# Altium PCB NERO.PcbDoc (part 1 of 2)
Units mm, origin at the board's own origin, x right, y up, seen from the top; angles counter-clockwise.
Board outline 53.3 x 68.53 mm, 2 copper layers (Top Layer[1], Bottom Layer[2]), stack 1.636 mm thick; 112 components, 60 nets, 397 pads, 225 vias.
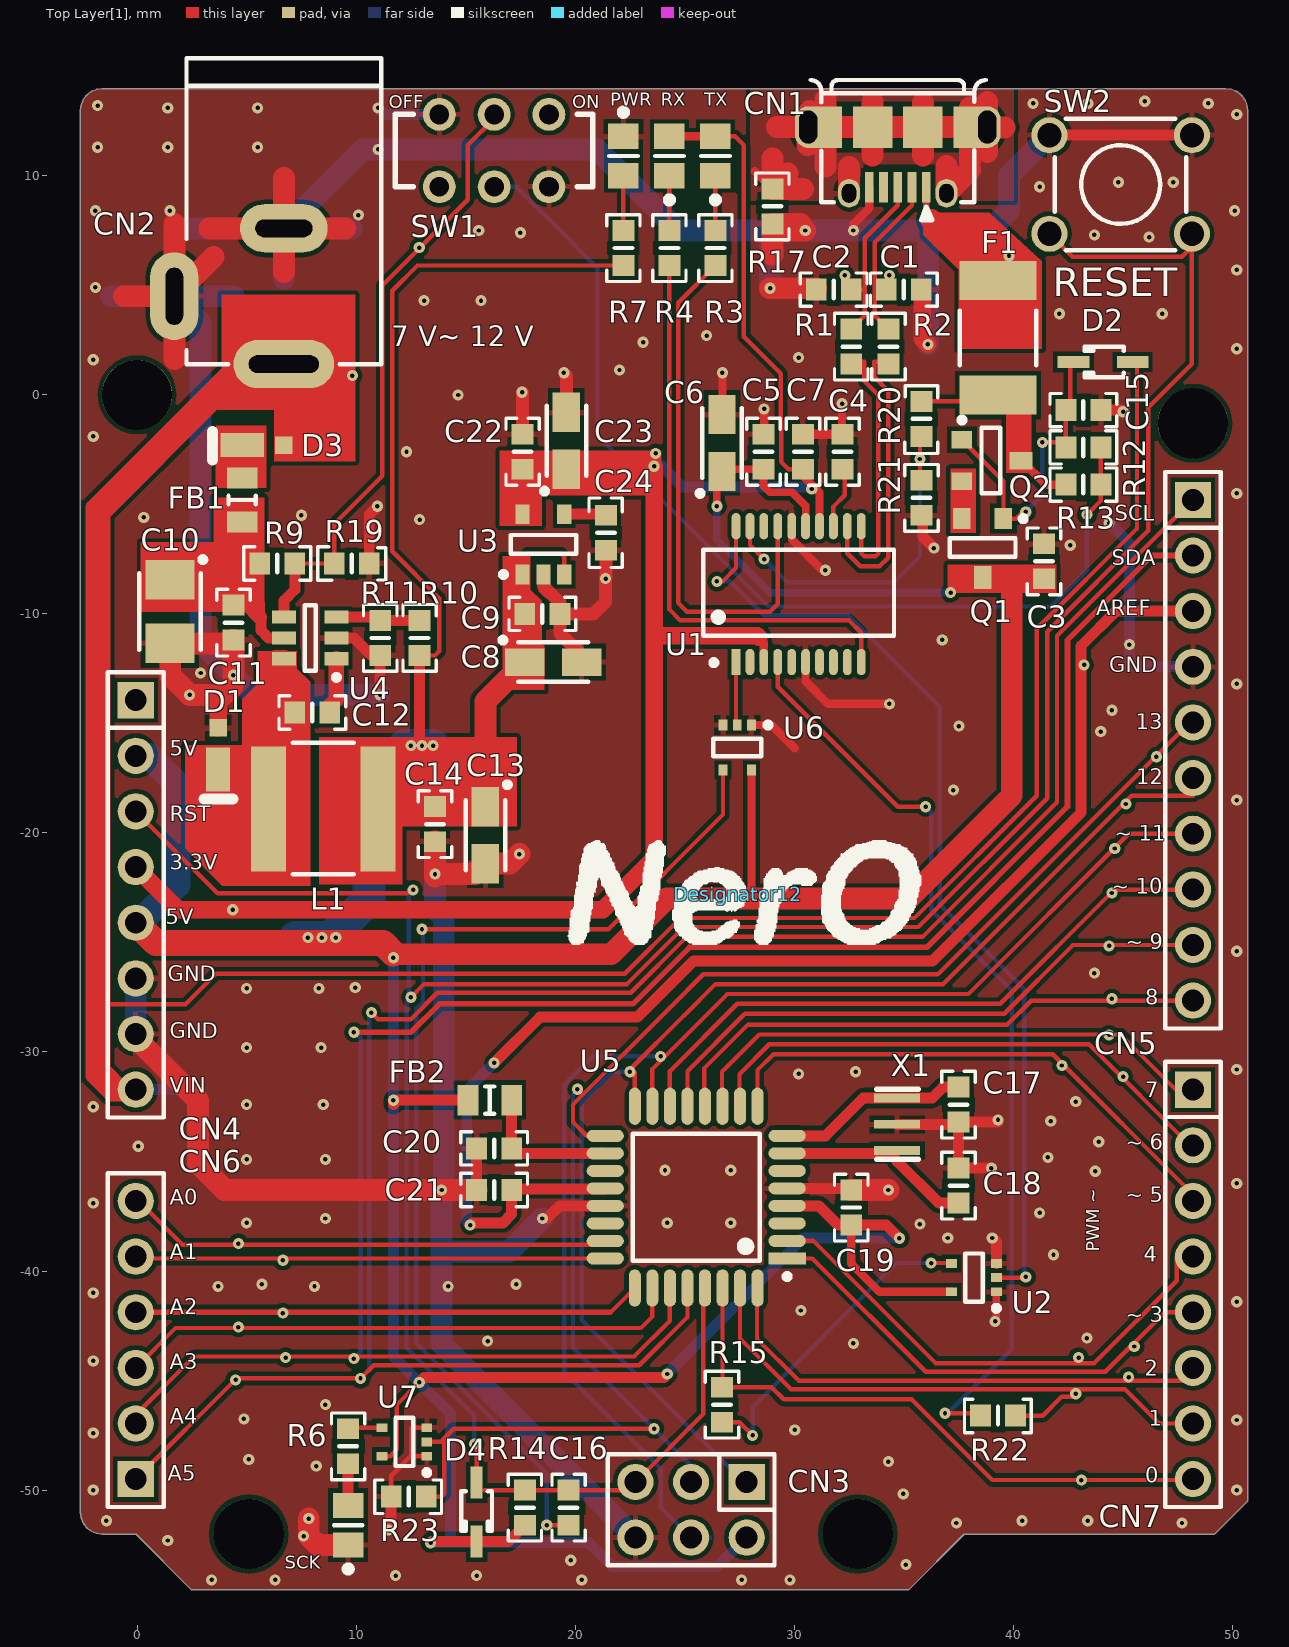
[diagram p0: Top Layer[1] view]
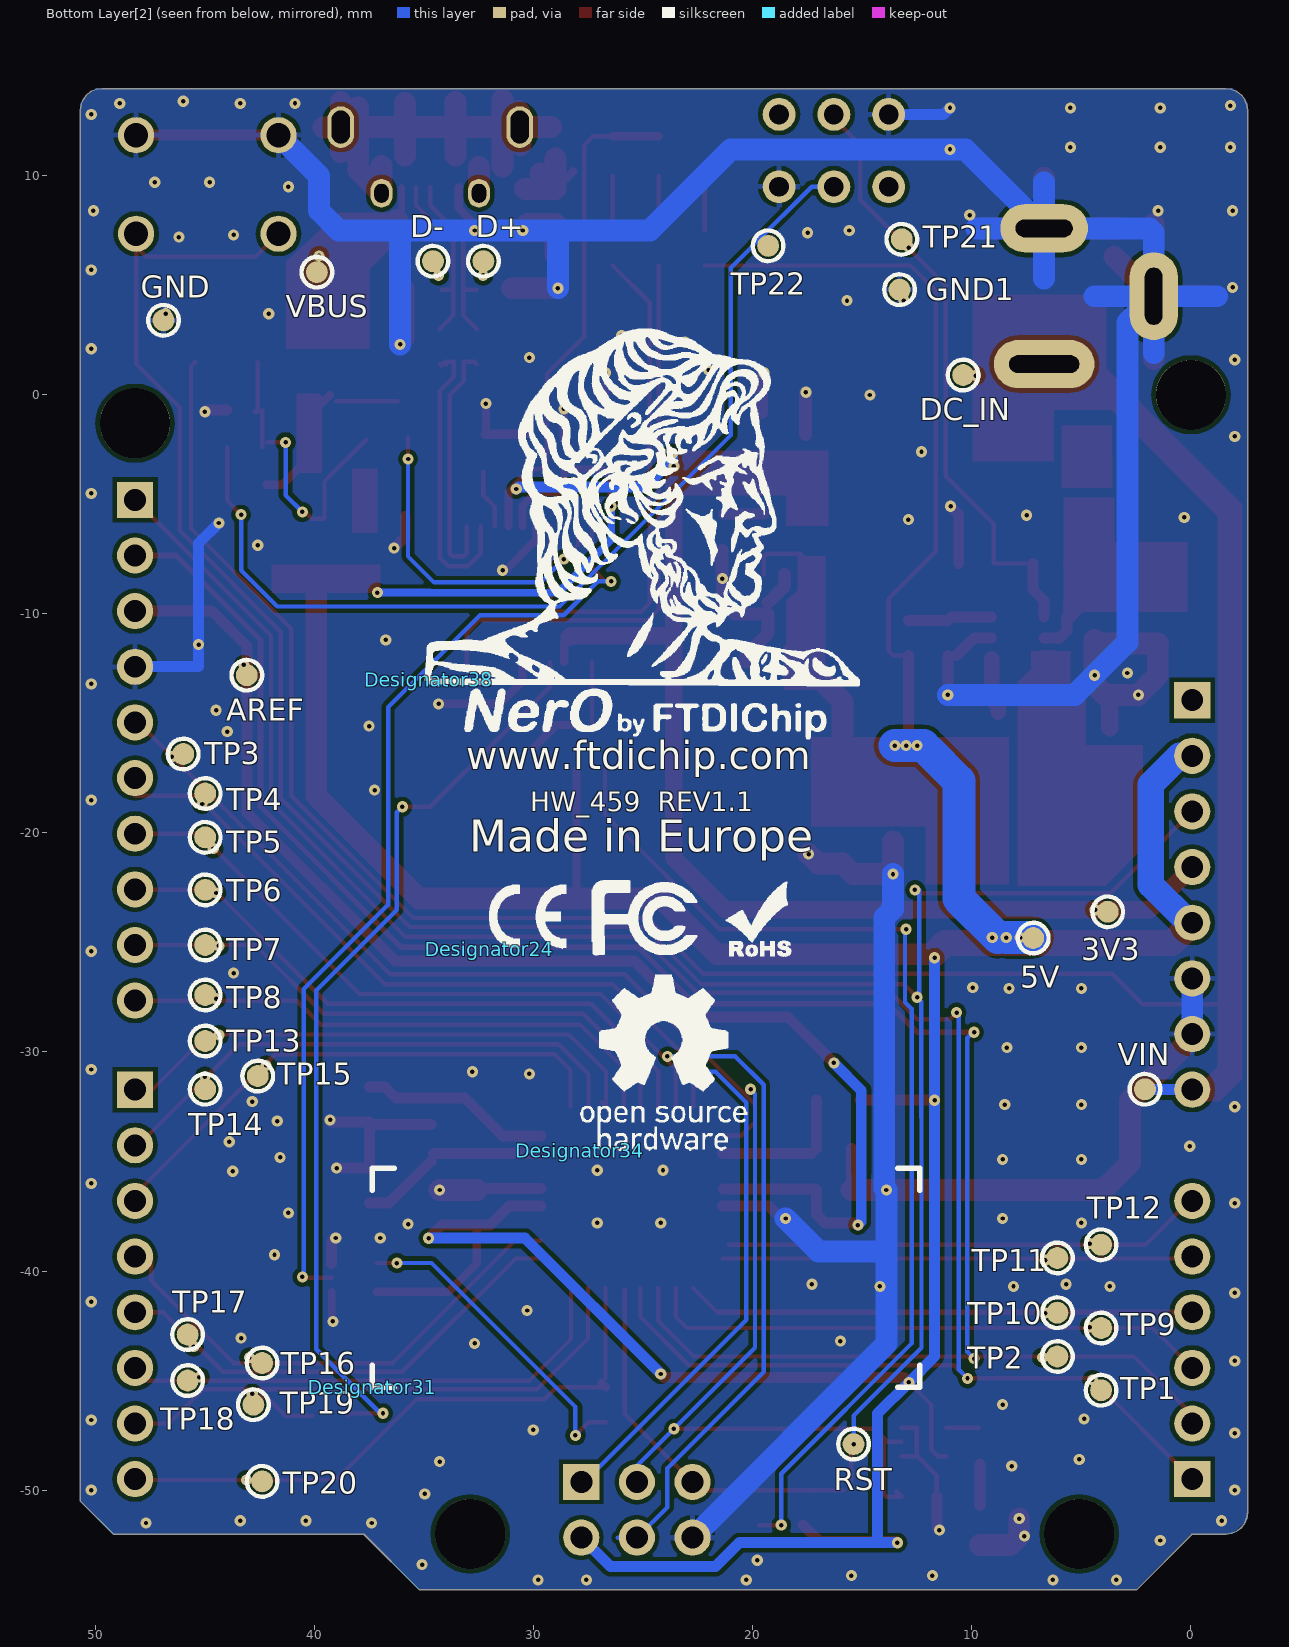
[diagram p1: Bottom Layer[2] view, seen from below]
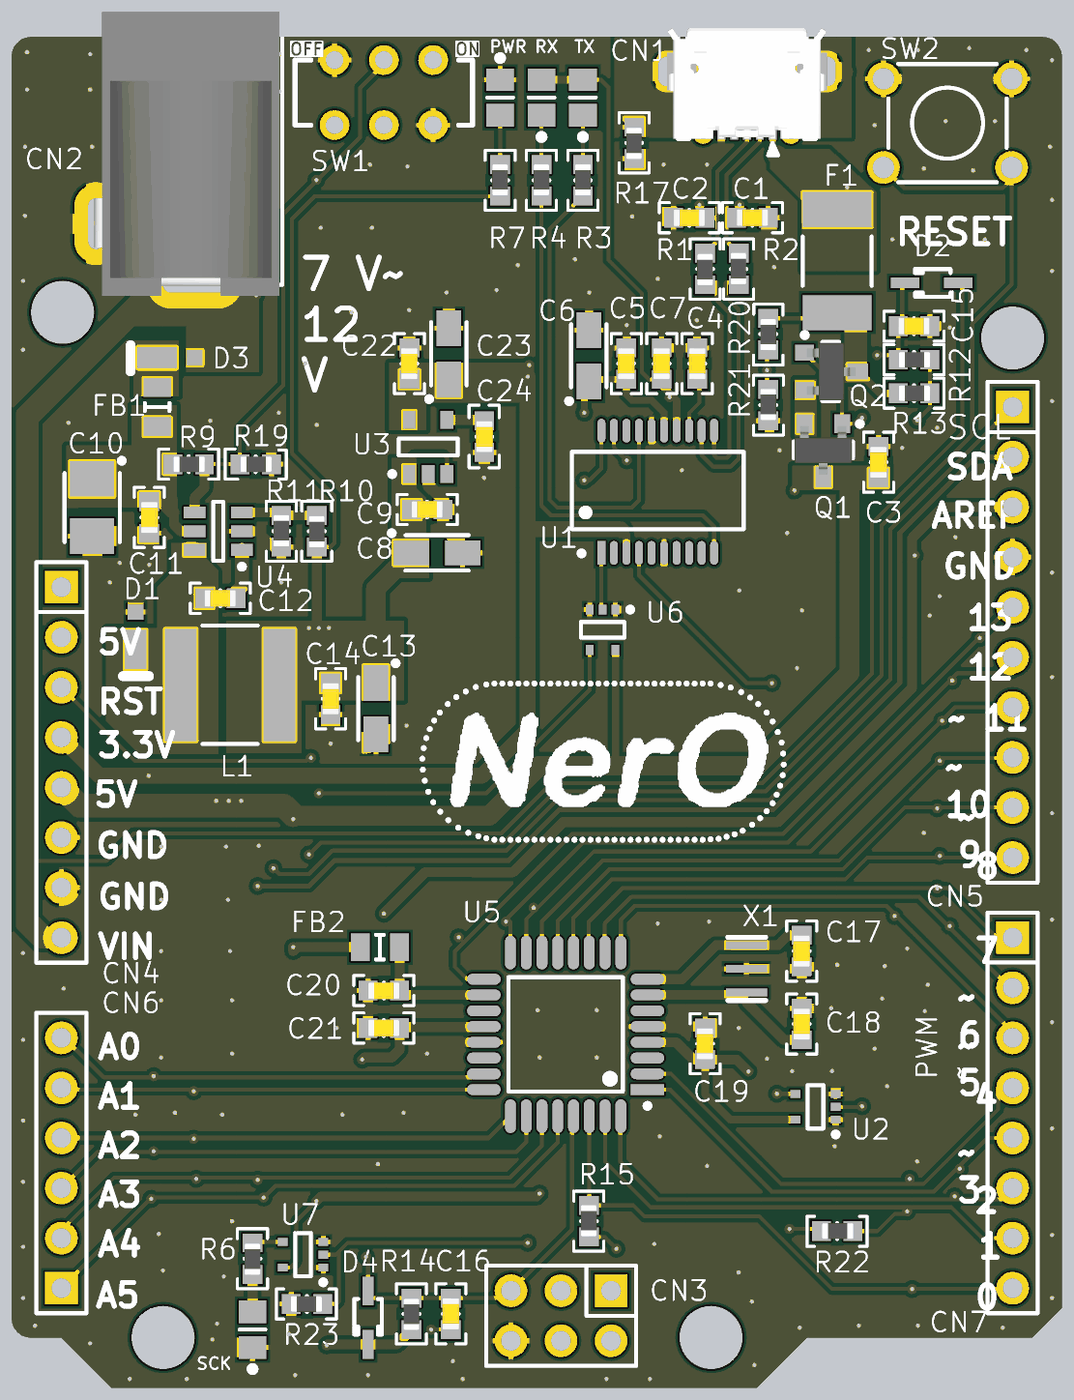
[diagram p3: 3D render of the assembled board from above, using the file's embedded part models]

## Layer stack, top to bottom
Top Layer[1]: signal copper 0.018
Dielectric: prepreg 1.6, FR4, Dk 4.8
Bottom Layer[2]: signal copper 0.018

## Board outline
-2.464,13.472 -2.295,13.684 -2.083,13.853 -1.851,13.938 -1.597,13.98 49.693,13.98 49.968,13.938 50.201,13.853 50.413,13.684 50.561,13.472 50.666,13.239 50.709,12.986 50.709,-50.492 49.185,-52.016 37.759,-52.016 35.22,-54.555 2.487,-54.555 -0.052,-52.016 -1.597,-52.016 -1.851,-51.973 -2.083,-51.889 -2.295,-51.719 -2.464,-51.508 -2.549,-51.275 -2.591,-51.021 -2.591,12.986 -2.549,13.239

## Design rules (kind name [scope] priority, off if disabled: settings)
Clearance [All] p1: gap=0.2
ComponentClearance [All] p1: gap=0.2 collisioncheckmode=3 verticalgap=0.2 showdistances=FALSE
DiffPairsRouting [All] p1: maxlimit=0.254 minlimit=0.254 mostfreqgap=0.254 maxuncoupledlength=12.7
FabricationTestPointUsage TestPointUsage [All] p1: valid=0 allowmultiple=FALSE
FabricationTestpoint Testpoint [All] p1: side=3 testpointundercomponent=TRUE minsize=1.016 maxsize=2.54 preferedsize=1.524 minholesize=0 maxholesize=1.016 preferedholesize=0.813 testpointgrid=0.025 allowsidetop=TRUE allowsidebottom=TRUE usegrid=TRUE gridtolerance=0
HoleSize [All] p1: absolutevalues=TRUE maxlimit=10 minlimit=0.025 maxpercent=80.000 minpercent=20.000
HoleToHoleClearance [All] p1: gap=0.25 allowstackedmicrovias=TRUE
MinimumSolderMaskSliver [All] p1: minsoldermaskwidth=0.1
PlaneClearance [All] p1: clearance=0.4
PlaneConnect [All] p1: planeconnectstyle=Relief reliefexpansion=0.4 reliefentries=4 reliefconductorwidth=0.25 reliefairgap=0.25
PolygonConnect PolygonConnect_VIA [isvia vs InNet(gnd)] p1: connectstyle=Direct reliefconductorwidth=0.25 reliefentries=4 polygonreliefangle="90 Angle"
PolygonConnect [All] p2: connectstyle=Relief reliefconductorwidth=0.25 reliefentries=4 polygonreliefangle="90 Angle"
RoutingVias [All] p1: holewidth=0.4 width=0.7 viastyle="Through Hole" minholewidth=0.4 minwidth=0.7 maxholewidth=0.6 maxwidth=0.9
SilkToSilkClearance [All] p1: silktosilkclearance=0.2
SilkscreenOverComponentPads [All] p1: minsilkscreentomaskgap=0.254
SolderMaskExpansion [All] p1: expansion=0.1
Width [All] p1: maxlimit=10 minlimit=0.2 preferedwidth=0.2 minimp=50.000000 maximp=50.000000 favimp=50.000000
17 further rules are at their usual default settings.

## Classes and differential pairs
component class nero: 3V3 5V AREF C1 C2 C3 C4 C5 C6 C7 C8 C9 C10 C11 C12 C13 C14 C15 C16 C17 C18 C19 C20 C21 C22 C23 C24 CN1 CN2 CN3 CN4 CN5 CN6 CN7 D1 D2 D3 D4 D+ D- DC_IN F1 FB1 FB2 GND GND1 L1 PWR Q1 Q2 R1 R2 R3 R4 R6 R7 R9 R10 R11 R12 R13 R14 R15 R17 R19 R20 R21 R22 R23 RST RX SCK SW1 SW2 TP21 TP22 TX U1 U2 U3 U4 U5 U6 U7 VBUS VIN X1
component class SCH_Revision_History: TP1 TP2 TP3 TP4 TP5 TP6 TP7 TP8 TP9 TP10 TP11 TP12 TP13 TP14 TP15 TP16 TP17 TP18 TP19 TP20
differential pair D: +D_P -D_N
differential pair USB: +USB_P -USB_N

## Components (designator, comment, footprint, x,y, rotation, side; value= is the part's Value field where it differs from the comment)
3V3 "SMT_TP" TP_SMT_1MM 3.8,-23.6 r180 bottom
5V "SMT_TP" TP_SMT_1MM 7.2,-24.8 r180 bottom
AREF "SMT_TP" TP_SMT_1MM 43.1,-12.8 r270 bottom
C1 "DNP" CAPC1608-0603 35,4.8 r0 top
C2 "DNP" CAPC1608-0603 31.8,4.8 r180 top
C3 "0.1UF" CAPC1608-0603 41.4,-7.6 r90 top
C4 "0.1UF" CAPC1608-0603 32.2,-2.6 r270 top
C5 "0.1UF" CAPC1608-0603 28.6,-2.6 r90 top
C6 "10uF" CAPM-A-3216-18 26.7,-2.2 r90 top
C7 "0.1UF" CAPC1608-0603 30.4,-2.6 r90 top
C8 "10uF" CAPM-A-3216-18 19,-12.2 r0 top
C9 "0.1UF" CAPC1608-0603 18.5,-10 r0 top
C10 "10UF/25V" CAPM-B-3528-21 1.5,-9.9 r270 top
C11 "0.1UF" CAPC1608-0603 4.4,-10.4 r270 top
C12 "0.1UF" CAPC1608-0603 8,-14.5 r180 top
C13 "10uF" CAPM-A-3216-18 15.9,-20.1 r270 top
C14 "0.1UF" CAPC1608-0603 13.6,-19.6 r270 top
C15 "1nF" CAPC1608-0603 43.2,-0.7 r0 top
C16 "0.1UF" CAPC1608-0603 19.7,-50.8 r90 top
C17 "15pF" CAPC1608-0603 37.5,-32.4 r90 top
C18 "15pF" CAPC1608-0603 37.5,-36.1 r270 top
C19 "0.1UF" CAPC1608-0603 32.6,-37.1 r90 top
C20 "0.1UF" CAPC1608-0603 16.3,-34.4 r180 top
C21 "0.1UF" CAPC1608-0603 16.3,-36.3 r0 top
C22 "0.1uF" CAPC1608-0603 17.6,-2.6 r90 top
C23 "10uF" CAPM-A-3216-18 19.6,-2.1 r90 top
C24 "10nF" CAPC1608-0603 21.4,-6.3 r270 top
CN1 "CN USB" CN_USB_MICRO_HOUSING 32.5,9.2 r0 top
CN2 "2.1mm PwrJack" "CN_2.1mm Power Socket routed pins" 6.7,7.6 r270 top
CN3 "TC2030-IDC-FP" CN_HDR2X3 27.829,-49.627 r180 top locked
CN4 "HEADER 8" CN_HDR1X8 -0.06,-13.94 r270 top locked
CN5 "HEADER 10" CN_HDR1X10 48.2,-4.796 r270 top locked
CN6 "HEADER 6" HDR1X6 -0.06,-49.5 r90 top locked
CN7 "HEADER 8" CN_HDR1X8 48.2,-31.72 r270 top locked
D1 "MSS1P3L" DIODE_MSS1P3L 3.7,-15.2 r90 top
D2 "1N4148" SOD-323 44.1,1.5 r0 top
D3 "MSS1P3L" DIODE_MSS1P3L 6.7,-2.3 r0 top
D4 "1N4148" SOD-323 15.5,-51 r90 top
D+ "SMT_TP" TP_SMT_1MM 32.3,6.1 r180 bottom
D- "SMT_TP" TP_SMT_1MM 34.6,6.1 r180 bottom
DC_IN "SMT_TP" TP_SMT_1MM 10.4,0.9 r180 bottom
Designator12 "Comment" LOGO_NERO1 19.9,-25.1 r0 top locked
Designator24 "Comment" logo_fcc_3 32.024,-25.318 r180 bottom
Designator31 "Comment" label_location 37.375,-45.305 r180 bottom
Designator34 "Comment" logo_oshw2 27.9,-34.5 r180 bottom
Designator38 "Comment" logo_nero_ftdi 34.8,-13 r180 bottom
F1 "1.1A" "Fuse_0ZCG Series" 39.3,2.6 r270 top
FB1 "600R/2A" IND_C2012-0805 4.8,-4.8 r90 top
FB2 "600R/2A" IND_C2012-0805 16.1,-32.2 r180 top
GND "SMT_TP" TP_SMT_1MM 46.9,3.4 r180 bottom
GND1 "SMT_TP" TP_SMT_1MM 13.3,4.8 r270 bottom
L1 "22UH" IND_NR6020 8.5,-18.9 r0 top
PWR "Green" LEDC2012-0805 22.2,10.9 r270 top
Q1 "IRLM6402PBF" SOT23-3AL 38.6,-7 r270 top
Q2 "IRLM6402PBF" SOT23-3AL 39,-3 r0 top
R1 "27R" RESC1608-0603 32.6,2.2 r270 top
R2 "27R" RESC1608-0603 34.3,2.2 r90 top
R3 "470R" RESC1608-0603 26.4,6.7 r90 top
R4 "470R" RESC1608-0603 24.3,6.7 r90 top
R6 "1K" RESC1608-0603 9.638,-48 r270 top
R7 "1K" RESC1608-0603 22.2,6.7 r90 top
R9 "47k" RESC1608-0603 6.4,-7.7 r0 top
R10 "47K5" RESC1608-0603 12.9,-11.1 r270 top
R11 "9K1" RESC1608-0603 11.1,-11.1 r90 top
R12 "47k" RESC1608-0603 43.2,-2.4 r0 top
R13 "47k" RESC1608-0603 43.2,-4.1 r0 top
R14 "10K" RESC1608-0603 17.7,-50.8 r270 top
R15 "1K" RESC1608-0603 26.7,-46.1 r90 top
R17 "0R" RESC1608-0603 29,8.6 r270 top
R19 "47K" RESC1608-0603 9.8,-7.7 r0 top
R20 "4K7" RESC1608-0603 35.8,-1.1 r270 top
R21 "10K" RESC1608-0603 35.8,-4.7 r90 top
R22 "1K" RESC1608-0603 39.3,-46.6 r0 top
R23 "10K" RESC1608-0603 12.4,-50.3 r180 top
RST "SMT_TP" TP_SMT_1MM 15.4,-47.9 r180 bottom
RX "Yellow" LEDC2012-0805 24.3,10.9 r90 top
SCK "Red" LEDC2012-0805 9.638,-51.6 r90 top
SW1 "SW-DPDT" SW_JS202011AQN 13.8,9.5 r180 top
SW2 "SW_PB" SW_PushButton 44.9,9.6 r180 top
TP1 "SMT_TP" TP_SMT_1MM 4.1,-45.44 r180 bottom
TP2 "SMT_TP" TP_SMT_1MM 6.1,-43.9 r180 bottom
TP3 "SMT_TP" TP_SMT_1MM 46,-16.4 r180 bottom
TP4 "SMT_TP" TP_SMT_1MM 45,-18.2 r180 bottom
TP5 "SMT_TP" TP_SMT_1MM 45,-20.2 r180 bottom
TP6 "SMT_TP" TP_SMT_1MM 45,-22.6 r180 bottom
TP7 "SMT_TP" TP_SMT_1MM 45,-25.116 r180 bottom
TP8 "SMT_TP" TP_SMT_1MM 45,-27.4 r180 bottom
TP9 "SMT_TP" TP_SMT_1MM 4.1,-42.6 r180 bottom
TP10 "SMT_TP" TP_SMT_1MM 6.1,-41.9 r270 bottom
TP11 "SMT_TP" TP_SMT_1MM 6.1,-39.4 r270 bottom
TP12 "SMT_TP" TP_SMT_1MM 4.1,-38.8 r270 bottom
TP13 "SMT_TP" TP_SMT_1MM 45,-29.5 r270 bottom
TP14 "SMT_TP" TP_SMT_1MM 45,-31.7 r270 bottom
TP15 "SMT_TP" TP_SMT_1MM 42.6,-31.1 r270 bottom
TP16 "SMT_TP" TP_SMT_1MM 42.4,-44.2 r270 bottom
TP17 "SMT_TP" TP_SMT_1MM 45.8,-42.9 r270 bottom
TP18 "SMT_TP" TP_SMT_1MM 45.8,-45 r270 bottom
TP19 "SMT_TP" TP_SMT_1MM 42.8,-46.1 r270 bottom
TP20 "SMT_TP" TP_SMT_1MM 42.4,-49.6 r270 bottom
TP21 "SMT_TP" TP_SMT_1MM 13.2,7.1 r270 bottom
TP22 "SMT_TP" TP_SMT_1MM 19.3,6.8 r270 bottom
TX "Yellow" LEDC2012-0805 26.4,10.9 r90 top
U1 "FT231XS" SSOP20 30.2,-9.1 r0 top
U2 "CAHCT1G125QDCKRQ1" SC70-5 38.2,-40.3 r180 top
U3 "SPX3819M5-L-3-3/TR" SOT23-5AL 17.6,-8.2 r90 top
U4 "AOZ1282CI" SOT23-6N 7.9,-11.1 r180 top
U5 "ATMEGA328P-AU" TQFP80P900X900X160-32N 25.525,-36.625 r180 top
U6 "CAHCT1G125QDCKRQ1" SC70-5 27.4,-16.1 r270 top
U7 "CAHCT1G125QDCKRQ1" SC70-5 12.2,-47.8 r180 top
VBUS "SMT_TP" TP_SMT_1MM 39.9,5.6 r270 bottom
VIN "SMT_TP" TP_SMT_1MM 2.1,-31.7 r180 bottom
X1 "16MHZ" CRYSTAL_16MHZ 34.7,-33.3 r90 top

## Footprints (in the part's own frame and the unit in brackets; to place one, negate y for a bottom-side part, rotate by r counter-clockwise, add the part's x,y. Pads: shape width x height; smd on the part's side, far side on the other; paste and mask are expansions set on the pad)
CAPC1608-0603 [mm] "Chip Capacitor; Body 1.6 x 0.8 mm (LxW typ)"
  rect 0.95x1 smd: 1(-0.8,0) 2(0.8,0)
  Top Layer[1] pour cut-out: -0.325,0.75 0.325,0.75 0.325,-0.75 -0.325,-0.75
  silkscreen extent -1.52,-0.76 1.52,0.76, body extent -0.8,-0.43 0.8,0.44, height 0.82
CAPM-A-3216-18 [mm] "Capacitor, SMT Tantalum; Body 3.2 x 1.6 mm (LxW typ)"
  rect 1.8x1.25 smd: 1(-1.3,0) 2(1.3,0)
  Top Layer[1] pour cut-out: -0.4,0.9 0.4,0.9 0.4,-0.9 -0.4,-0.9
  silkscreen extent -2.4,-0.9 1.6,1.1, body extent -1.6,-0.8 1.6,0.8, height 1.8
CAPM-B-3528-21 [mm] "Capacitor, SMT Tantalum; Body 3.5 x 2.8 mm (LxW typ)"
  rect 1.8x2.25 smd: 1(-1.45,0) 2(1.45,0)
  Top Layer[1] pour cut-out: -0.55,1.4 0.55,1.4 0.55,-1.4 -0.55,-1.4
  silkscreen extent -2.47,-1.4 1.75,1.6, body extent -1.75,-1.4 1.75,1.4, height 1.8
"CN_2.1mm Power Socket routed pins" [mm] "2.1mm Power Jack; DK cat.No. CP-002A-ND; CUI Inc. PJ-002A"
  oval 2.2x4 hole 0.8 slot 2.6 at 90 deg: 1(0,0)
  oval 4x2.2 hole 0.8 slot 2.6 at 0 deg: 2(3.1,-5)
  oval 2.2x4.6 hole 0.8 slot 3.2 at 90 deg: 3(6.2,0)
  silkscreen extent -7.77,-4.45 6.2,4.45, body extent -7.64,-5.09 6.76,4.31, height 11.02
CN_HDR1X8 [mil] "Connector; Header; 8 Position; pitch 0.1\""
  rect 65x65 hole 39.37: 1(0,0)
  round 65 hole 39.37: 2(100,0) 3(200,0) 4(300,0) 5(400,0) 6(500,0) 7(600,0) 8(700,0)
  silkscreen extent -50,-50 750,50
CN_HDR1X10 [mil] "Connector; Header; 10 Position; pitch 0.1\""
  rect 65x65 hole 39.37: 1(0,0)
  round 65 hole 39.37: 2(100,0) 3(200,0) 4(300,0) 5(400,0) 6(500,0) 7(600,0) 8(700,0) 9(800,0) 10(900,0)
  silkscreen extent -50,-50 950,50
CN_HDR2X3 [mil] "Connector; Header; 2x3 Position; pitch 0.1\""
  rect 65x65 hole 39.37: 1(0,0)
  round 65 hole 39.37: 2(0,100) 3(100,0) 4(100,100) 5(200,0) 6(200,100)
  silkscreen extent -50,-50 250,150
CN_USB_MICRO_HOUSING [mm] "Micro_USB2.0_SMT_Housing Holes"
  rect 0.4x1.4 smd: 1(3.525,0.27) 2(2.875,0.27) 3(2.225,0.27) 4(1.575,0.27) 5(0.925,0.27)
  oval 1.23x1.9 hole 0.83 slot 1.5 at 90 deg: 6(-1.86,3.02) 7(6.31,3.02)
  rect 1.5x1.9 smd: 6(-1.075,3.02) 7(5.525,3.02)
  oval 1x1.3 hole 0.65 slot 0.85 at 90 deg: 8(0,0) 9(4.45,0)
  rect 1.8x1.9 smd: 9(1.075,3.02) 9(3.375,3.02)
  silkscreen extent -1.75,-1.23 6.25,5.17, body extent -1.81,-0.38 6.26,5.22, height 2.77
CRYSTAL_16MHZ [mm] "CRYSTAL SMT 16MHZ"
  rect 0.4x2.1 smd: 1(1.2,0) 2(0,0) 3(-1.2,0)
  silkscreen extent -1.6,-0.97 1.6,0.94
DIODE_MSS1P3L [mm] "DIODE_MSS1P3L MICRO_SMP"
  rect 2x1.1 smd: 1(-1.9,0)
  rect 0.8x0.8 smd: 2(0,0)
  silkscreen extent -3.25,-0.69 -3.25,0.63
"Fuse_0ZCG Series" [mm] "Fuse SMT; 0ZCG Series - 1812 Chip; Bel Fuse"
  rect 1.78x3.5 smd: 1(-2.615,0) 2(2.615,0)
  silkscreen extent -1.25,-1.75 1.25,1.75, body extent -2.27,-1.62 2.27,1.62
HDR1X6 [mil] "Connector; Header; 6 Position"
  rect 65x65 hole 39.37: 1(0,0)
  round 65 hole 39.37: 2(100,0) 3(200,0) 4(300,0) 5(400,0) 6(500,0)
  silkscreen extent -50,-50 550,50
IND_C2012-0805 [mm] "Chip Inductor; Body 2 x 1.2 mm (LxW typ)"
  rect 0.95x1.4 smd: 1(-1,0) 2(1,0)
  Top Layer[1] pour cut-out: -0.525,0.9 0.525,0.9 0.525,-0.9 -0.525,-0.9
  silkscreen extent -0.2,-0.63 0.2,0.63, body extent -1,-0.63 1,0.63, height 1
IND_NR6020 [mm] "Inductor, NR6020 series, Taiyo Yuden"
  rect 1.6x5.7 smd: 1(-2.5,0) 2(2.5,0)
  silkscreen extent -1.4,-2.99 1.4,3.01, body extent -3,-2.99 3,3.01, height 2
label_location [mm]
  silkscreen extent 0,0 25,10
LEDC2012-0805 [mm] "Chip LED diode; Body 2 x 1.3 mm (LxW typ)"
  rect 1.15x1.4 smd: 1(-0.9,0) 2(0.9,0)
  Top Layer[1] pour cut-out: -0.325,0.9 0.325,0.9 0.325,-0.9 -0.325,-0.9
  silkscreen extent -2.15,-0.65 0,0.65, body extent -1,-0.63 1,0.63, height 1
logo_fcc_3 [mm]
  silkscreen extent -0.02,-0.34 13.78,3.14
LOGO_NERO1 [mm]
  round 0.3 on Top Overlay: 0(0.686,-1.295) 0(2.413,6.274) 0(2.819,-1.651) 0(4.445,6.274) 0(5.258,-1.651) 0(6.071,-1.651) 0(6.477,6.274) 0(8.103,-1.651) 0(8.509,6.274) 0(9.322,6.274) 0(10.135,-1.651) 0(11.76,6.274) 0(12.167,-1.651) 0(13.995,6.071) 1(1.194,-1.473) 1(2.007,6.274) 1(3.226,-1.651) 1(4.039,6.274) 1(5.664,-1.651) 1(6.071,6.274) 1(6.477,-1.651) 1(8.103,6.274) 1(8.509,-1.651) 1(8.915,6.274) 1(10.541,-1.651) 1(11.354,6.274) 1(12.573,-1.651) 1(13.487,6.198) 2(1.6,-1.575) 2(1.6,6.223) 2(3.632,-1.651) 2(3.632,6.274) 2(5.664,6.274) 2(6.883,-1.651) 2(7.696,6.274) 2(8.915,-1.651) 2(10.947,-1.651) 2(10.947,6.274) 2(12.979,-1.626) 2(12.979,6.274) 3(1.067,6.096) 3(2.007,-1.651) 3(3.226,6.274) 3(4.039,-1.651) 3(5.258,6.274) 3(7.29,-1.651) 3(7.29,6.274) 3(9.322,-1.651) 3(10.541,6.274) 3(11.354,-1.651) 3(12.573,6.274) 3(13.386,-1.6) 4(-1.651,2.464) 4(-1.626,1.905) 4(-1.575,2.997) 4(-1.524,1.346) 4(-1.448,3.505) 4(-1.346,0.787) 4(-1.27,3.962) 4(-1.092,0.254) 4(-1.041,4.394) 4(-0.762,4.801) 4(-0.737,-0.229) 4(-0.356,5.232) 4(-0.33,-0.66) 4(0.076,5.588) 4(0.178,-1.041) 4(0.559,5.867) 4(2.413,-1.645) 4(2.819,6.268) 4(4.445,-1.645) 4(4.851,6.268) 4(6.883,6.268) 4(7.696,-1.645) 4(9.728,-1.645) 4(10.135,6.268) 4(11.76,-1.645) 4(12.167,6.268) 4(13.792,-1.499) 4(14.529,5.842) 4(14.605,-1.194) 4(14.986,5.563) 4(15.088,-0.889) 4(15.392,5.232) 4(15.494,-0.559) 4(15.824,-0.203) 4(15.824,4.801) 4(16.129,0.203) 4(16.129,4.343) 4(16.332,0.635) 4(16.383,3.81) 4(16.51,1.092) 4(16.586,3.277) 4(16.637,1.626) 4(16.662,2.718) 4(16.688,2.159) 9(14.199,-1.372) 10(4.851,-1.651) 10(9.728,6.274)
  silkscreen extent -0.25,0.03 15.9,4.78
logo_nero_ftdi [mm]
  silkscreen extent -0.18,-2.72 19.68,16
logo_oshw2 [mm]
  silkscreen extent 0.02,0 7.64,8
RESC1608-0603 [mm] "Chip Resistor; Body 1.6 x 0.8 mm (LxW typ)"
  rect 0.95x1 smd: 1(-0.8,0) 2(0.8,0)
  Top Layer[1] pour cut-out: -0.325,-0.755 -0.325,0.75 0.325,0.75 0.325,-0.755
  silkscreen extent -1.52,-0.76 1.52,0.76, body extent -0.77,-0.4 0.83,0.4, height 0.57
SC70-5 [mm] "SC70, 5-Leads, Body 2.0x1.3mm, Pitch 0.65mm, Lead Span 2.1mm"
  rect 0.5x0.4 smd: 1(-1.025,0.65) 2(-1.025,0) 3(-1.025,-0.65) 4(1.025,-0.65) 5(1.025,0.65)
  silkscreen extent -1.15,-1.1 0.4,1.52, body extent -0.7,-1.1 0.7,1.1, height 1.1
SOD-323 [mm] "SOD-323/SC-76; 2 Leads; Body 1.8 x 1.4 mm, (LxW)"
  rect 1.45x0.55 smd: 1(-1.35,0) 2(1.35,0)
  silkscreen extent -0.85,-0.7 0.95,0.7, body extent -0.85,-0.7 0.95,0.7
SOT23-3AL [mm] "SOT23 SMT Package"
  rect 0.95x0.8 smd: 1(-1.35,0.95) 2(-1.35,-0.95)
  rect 1.05x0.8 smd: 3(1.35,0)
  silkscreen extent -1.47,-1.5 0.4,1.97, body extent -1.24,-1.47 1.23,1.45, height 0.95
SOT23-5AL [mm] "SOT23, 5-Leads, Body 2.9x1.6mm, Pitch 0.95mm, Lead Span 2.8mm"
  rect 0.9x0.65 smd: 1(0,0) 2(0,-0.95) 3(0,-1.9) 4(2.75,-1.9) 5(2.75,0)
  silkscreen extent -0.12,-2.45 1.8,1, body extent 0.5,-2.45 2.25,0.55
SOT23-6N [mm] "SOT23, 6-Leads, Body 3.0x3.0mm (max), Pitch 0.95mm, IPC Medium Density"
  rect 1.1x0.6 smd: 1(-1.2,0.95) 2(-1.2,0) 3(-1.2,-0.95) 4(1.2,-0.95) 5(1.2,0) 6(1.2,0.95)
  silkscreen extent -1.33,-1.5 0.25,1.92, body extent -0.87,-1.52 0.87,1.53, height 1.45
SSOP20 [mm] "SSOP20"
  rect 0.4x1.2 smd: 1(-2.857,-3.1)
  oval 0.4x1.2 smd: 2(-2.222,-3.1) 3(-1.587,-3.1) 4(-0.953,-3.1) 5(-0.318,-3.1) 6(0.318,-3.1) 7(0.953,-3.1) 8(1.587,-3.1) 9(2.222,-3.1) 10(2.857,-3.1) 11(2.857,3.1) 12(2.222,3.1) 13(1.587,3.1) 14(0.953,3.1) 15(0.318,3.1) 16(-0.318,3.1) 17(-0.953,3.1) 18(-1.587,3.1) 19(-2.222,3.1) 20(-2.857,3.1)
  silkscreen extent -4.36,-3.25 4.36,2.03, body extent -4.34,-2.35 4.28,2.36
SW_JS202011AQN [mm] "PTH  DPDT SW R/A"
  round 1.5 hole 0.9: 1(-5,-3.3) 2(-2.5,-3.3) 3(0,-3.3) 4(0,0) 5(-2.5,0) 6(-5,0)
  silkscreen extent -7,-3.3 2.01,0
SW_PushButton [mm] "Push button switch"
  round 1.651 hole 1.1: 1(-3.25,-2.25) 2(3.25,-2.25) 3(-3.25,2.25) 4(3.25,2.25)
  silkscreen extent -3,-3 3,3, body extent -3,-3 3,3
TP_SMT_1MM [mm]
  round 1 smd paste-1: TP(0,0)
  silkscreen extent -0.7,-0.7 0.7,0.7
TQFP80P900X900X160-32N [mm] "TQFP, 32-Leads, Body 9.2x9.2mm (max), Pitch 0.80mm, IPC Medium Density"
  rect 1.7x0.55 smd: 1(-4.15,2.8)
  oval 1.7x0.55 smd: 2(-4.15,2) 3(-4.15,1.2) 4(-4.15,0.4) 5(-4.15,-0.4) 6(-4.15,-1.2) 7(-4.15,-2) 8(-4.15,-2.8) 17(4.15,-2.8) 18(4.15,-2) 19(4.15,-1.2) 20(4.15,-0.4) 21(4.15,0.4) 22(4.15,1.2) 23(4.15,2) 24(4.15,2.8)
  oval 0.55x1.7 smd: 9(-2.8,-4.15) 10(-2,-4.15) 11(-1.2,-4.15) 12(-0.4,-4.15) 13(0.4,-4.15) 14(1.2,-4.15) 15(2,-4.15) 16(2.8,-4.15) 25(2.8,4.15) 26(2,4.15) 27(1.2,4.15) 28(0.4,4.15) 29(-0.4,4.15) 30(-1.2,4.15) 31(-2,4.15) 32(-2.8,4.15)
  silkscreen extent -4.28,-2.9 2.9,3.75, body extent -3.5,-3.5 3.5,3.5, height 1.6

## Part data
3V3 5V AREF D+ D- DC_IN GND GND1 RST TP1 TP2 TP3 TP4 TP5 TP6 TP7 TP8 TP9 TP10 TP11 TP12 TP13 TP14 TP15 TP16 TP17 TP18 TP19 TP20 TP21 TP22 VBUS VIN: library part TP_SMT_1mm
C1 C2 C3 C4 C5 C7 C9 C11 C12 C14 C15 C16 C17 C18 C19 C20 C21 C22 C24: library part CAP_SEMI, "Capacitor bipolar"
C6 C8 C10 C13 C23: library part CAP_POL, "Polarized Capacitor"
CN1: library part CN_USB_MINI_B, "Mini USB connector; SMD"
CN2: library part "CN_Power Jack", "Low Voltage Power Supply Connector"
CN3: library part "CN_HEADER 2x3", "ISP Connector, 6-Pin, Dual row, pitch 0.05\"; Tag-Connect; TC2030-IDC-FP"
CN4 CN7: library part "CN_HEADER 8", "Header, 8-Pin"
CN5: library part "CN_HEADER 10", "Header, 10-Pin"
CN6: library part "CN_HEADER 6", "Header, 6-Pin"
D1 D3: library part D_ZENER, "Zener Diode"
D2 D4: library part D_UNI, "DIODE SWITCH 75V 200MW SOD323"
F1: library part "FUSE 2", "Fuse"
FB1 FB2: library part FERRITE_BEAD, "Chip Ferrite Bead 0805"
L1: library part IND_POWER, "Magnetic-Core Inductor"
PWR RX SCK TX: library part D_LED, "Typical LED diode"
Q1 Q2: library part T_MOSFET-P, "P-Channel MOSFET; SOT-23"
R1 R2 R3 R4 R6 R7 R9 R10 R11 R12 R13 R14 R15 R17 R19 R20 R21 R22 R23: library part RES1, "Resistor"
SW1: library part SW-SPDT, "SPDT Switch"
SW2: library part SW_PB_4PIN, "Push button momentary switch"
U1: library part IC_FT231XS, "FT231XS-SSOP-20"
U2 U6 U7: library part IC_SN74LVC1G125DBVR, "IC BUS BUFF GATE 3ST SGL SC70-5"
U3: library part IC_AIC1733, "500mA, Low Dropout Linear Regulator  with Shutdown"
U4: "IC REG BUCK ADJ 1.2A SOT23-6"
U5: library part IC_ATMEGA328P-AU, "IC MCU 8BIT 32KB FLASH 32TQFP"
X1: library part XTAL, "Crystal Oscillator"

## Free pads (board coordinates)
  round 3.2 hole 3.2 unplated: 0(48.2,-1.3) 1(32.9,-52) 2(5.1,-52) 3(0,0)

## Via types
v1: diameter 0.508, hole 0.203, Top Layer[1] to Bottom Layer[2], tented both sides, 225 vias

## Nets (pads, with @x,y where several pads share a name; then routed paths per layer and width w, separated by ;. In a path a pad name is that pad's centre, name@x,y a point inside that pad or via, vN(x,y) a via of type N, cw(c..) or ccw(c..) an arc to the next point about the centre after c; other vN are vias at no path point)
3.3V: 3V3.TP C7.1 C22.1 C23.1 CN4.4 RX.2 TX.2 U1.3 U1.14 U3.5 | length 88.5
  Top Layer[1] w0.2: TX.2@26.4,11.8 27.3,11.8 27.7,11.4 27.7,2.657 29.389,0.968 29.389,-1.19 29.4,-1.201 29.4,-3.058 29.742,-3.4 30.1,-3.4 C7.1@30.4,-3.4
  Top Layer[1] w0.38: RX.2@24.3,11.8 TX.2@26.4,11.8 ; 28.373,-11.059 28.613,-11.299 U1.3@28.613,-12.2 ; C7.1@30.1,-3.4 31.153,-4.453 U1.14@31.153,-6
  Top Layer[1] w0.5: U3.5@17.6,-5.45 C22.1@17.6,-3.4 C23.1@19.6,-3.4 23.459,-3.4 v1(23.6,-3.259)
  Top Layer[1] w0.8: CN4.4@-0.06,-21.56 1.885,-23.505 v1(4.37,-23.505) 21.261,-23.505 23.6,-21.166 v1(23.6,-3.259) ; 23.668,-11 28.314,-11 28.373,-11.059
  Bottom Layer[2] w0.5: v1(23.6,-3.259) 23.959,-3.259 24.901,-4.201 30.701,-4.201 v1(30.8,-4.3) ; v1@23.674,-3.185 v1(23.674,-2.677)
+5V: 5V.TP C3.1 C5.1 C6.1 C8.1 C9.1 C13.1 C14.1 C19.1 CN3.2 CN4.2 CN4.5 D4.1 FB2.2 L1.2 Q1.3 R7.1 R10.2 R14.2 U1.15 U2.5 U3.1 U3.3 U5.4 U6.5 U7.5 | length 256.3
  Top Layer[1] w0.2: U7.5@11.175,-48.45 11.556,-48.45 11.863,-48.143 11.863,-46.095 v1(12.879,-45.079) ; R10.2@12.9,-11.9 13.6,-11.9 13.8,-11.7 13.8,-9.3 11.646,-7.146 11.646,4.746 12.8,5.9 R7.1@22.2,5.9 ; U3.1@17.6,-8.2 17.6,-7.481 17.832,-7.249 19.356,-7.249 19.5,-7.393 U3.3@19.5,-8.2
  Top Layer[1] w0.35: v1(26.468,-5.09) 26.468,-3.732 C6.1@26.7,-3.5 26.8,-3.4 C5.1@28.6,-3.4 28.6,-4.174 28.881,-4.455 29.897,-4.455 30.518,-5.076 U1.15@30.518,-6 ; v1(37.136,-9.027) 37.813,-8.35 Q1.3@38.6,-8.35 39.93,-8.35 C3.1@41.35,-8.35
  Top Layer[1] w0.38: 28.05,-23.027 28.05,-22.997 U6.5@28.05,-17.125 ; C19.1@32.6,-37.9 32.6,-39.657 33.893,-40.95 ; 33.915,-40.95 U2.5@37.175,-40.95
  Top Layer[1] w0.5: v1(11.7,-32.2) 11.7,-32.4 11.9,-32.2 FB2.2@15.1,-32.2 ; v1(12.879,-45.079) 13.108,-44.85 v1@24.05,-44.85 ; 12.9,-18.779 R10.2@12.9,-11.9 ; v1@13.45,-52.35 D4.1@15.5,-52.35 16.95,-52.35 R14.2@17.7,-51.6 ; U5.4@29.675,-37.025 31.125,-37.025 ; 31.15,-37.05 32,-37.9 C19.1@32.6,-37.9 34.2,-37.9 v1(34.8,-38.5)
  Top Layer[1] w0.6: C9.1@17.6,-9.9 U3.1@17.6,-8.2
  Top Layer[1] w0.8: v1(11.7,-25.7) v1@11.7,-25.5 ; C8.1@17.7,-12.2 C9.1@17.7,-10 ; 32.297,-22.997 32.396,-23.096
  Top Layer[1] w1: CN4.5@-0.06,-24.1 CN4.5@0.29,-24.45 ; L1.2@11.1,-18.8 C14.1@13.6,-18.8 C13.1@15.9,-18.8 15.9,-14 C8.1@17.7,-12.2 ; v1@11.736,-25.537 21.642,-25.537 24.182,-22.997 28.05,-22.997 32.297,-22.997 35.231,-22.997 39.93,-18.298 39.93,-8.35
  Top Layer[1] w1.2: CN4.5@-0.06,-24.1 0.869,-25.029 11.229,-25.029 v1@11.7,-25.5
  Bottom Layer[2] w0.35: v1(26.468,-5.09) 26.468,-6.614 28.894,-9.04 34.747,-9.04 34.76,-9.027 v1@36.976,-9.027
  Bottom Layer[2] w0.5: v1@11.696,-32.196 v1(11.7,-32.2) ; v1(11.7,-25.7) v1(11.7,-32.2) ; v1(13.4,-52.4) 14.3,-52.4 ; v1(24.2,-44.7) 30.4,-38.5 v1(34.8,-38.5) ; CN3.2@27.829,-52.167 26.504,-53.493 21.698,-53.493 20.605,-52.4 14.3,-52.4 ; v1(11.7,-32.2) 11.7,-43.9 v1(12.879,-45.079) 14.3,-46.5 14.3,-52.4
  Bottom Layer[2] w1: v1(8.434,-24.775) v1@8.815,-24.775
  Bottom Layer[2] w1.2: CN4.5@-0.06,-24.1 CN4.5@-0.035,-24.1 ; CN4.2@-0.06,-16.48 0.52,-16.48 1.83,-17.79 1.83,-22.21 ; CN4.5@-0.035,-24.227 CN4.5@-0.035,-24.1 ; 1.83,-22.362 0.092,-24.1 CN4.5@-0.035,-24.1
  Bottom Layer[2] w1.5: 5V.TP@7.226,-24.775 v1(7.799,-24.775) v1(8.434,-24.775) ; v1@8.815,-24.775 10.593,-22.997 10.593,-17.627 11.99,-16.23 ; 12.208,-16.012 v1(13.514,-16.012)
  other v1: 9.069,-24.775 12.498,-16.012 13.006,-16.012
AD0: CN6.6 TP12.TP U5.23 | length 22
  Top Layer[1] w0.2: CN6.6@0.075,-36.8 2.075,-38.8 4.116,-38.8 U5.23@21.1,-38.8
  Top Layer[1] w0.254: CN6.6@0.075,-36.975 CN6.6@0.075,-36.8
  other v1: 4.624,-38.745
AD1: CN6.5 TP11.TP U5.24 | length 21.3
  Top Layer[1] w0.2: CN6.5@0.025,-39.425 U5.24@21.375,-39.425
  other v1: 6.656,-39.507
AD2: CN6.4 TP10.TP U5.25 | length 23.2
  Top Layer[1] w0.2: 21.612,-41.888 U5.25@22.725,-40.775
  Top Layer[1] w0.254: CN6.4@-0.06,-41.88 21.604,-41.88
  other v1: 6.656,-41.92
AD3: CN6.3 TP9.TP U5.26 | length 25.9
  Top Layer[1] w0.2: CN6.3@-0.06,-44.42 1.76,-42.6 23,-42.6 23.525,-42.075 U5.26@23.525,-40.775
  other v1: 4.624,-42.555
AD4/SDA: CN5.2 CN6.2 TP2.TP U5.27 | length 94.9
  Top Layer[1] w0.2: CN6.2@-0.06,-46.56 2.6,-43.9 22.689,-43.9 24.325,-42.264 U5.27@24.325,-40.775
  Top Layer[1] w0.254: CN6.2@-0.06,-46.96 CN6.2@-0.06,-46.56 ; v1(9.9,-29.1) 12.504,-29.1 13.804,-27.8 22.635,-27.8 25.212,-25.223 36.049,-25.223 42.473,-18.799 42.473,-11.198 46.335,-7.336 CN5.2@48.2,-7.336
  Bottom Layer[2] w0.2: v1(9.9,-44) 10.204,-43.696 10.204,-29.347 v1@9.957,-29.1
  other v1: 6.783,-43.952
AD5/SCL: CN5.1 CN6.1 TP1.TP U5.28 | length 98.5
  Top Layer[1] w0.2: CN6.1@-0.06,-49.5 4.54,-44.9 v1(10.2,-44.9) 10.8,-44.3 22.925,-44.3 25.125,-42.1 U5.28@25.125,-40.775 ; v1(10.7,-28.2) 11,-28.5 12.5,-28.5 13.7,-27.3 22.531,-27.3 25.085,-24.746 35.854,-24.746 41.996,-18.604 41.996,-11 CN5.1@48.2,-4.796
  Top Layer[1] w0.254: CN6.1@-0.06,-49.5 CN6.1@0.2,-49.5
  Bottom Layer[2] w0.2: v1(10.2,-44.9) 10.604,-44.496 v1@10.604,-28.296
  other v1: 4.497,-44.968
AREF: AREF.TP C21.2 CN5.3 U5.20 | length 60.4
  Top Layer[1] w0.5: v1(15.2,-37.9) 15.3,-37.8 16.7,-37.8 17.1,-37.4 C21.2@17.1,-36.3 17.15,-36.25 U5.20@21.35,-36.25 ; v1(16.3,-30.5) 18.404,-28.396 20.792,-28.396 20.796,-28.4 22.851,-28.4 25.401,-25.85 36.308,-25.85 43.1,-19.058 43.1,-11.457 44.681,-9.876 CN5.3@48.2,-9.876
  Bottom Layer[2] w0.5: v1(15.2,-37.9) 15.05,-37.75 15.05,-31.75 v1(16.3,-30.5)
  other v1: 43.232,-12.329
AVCC: C20.1 FB2.1 U5.18 | length 6.5
  Top Layer[1] w0.254: U5.18@21.227,-34.477 U5.18@21.375,-34.625
  Top Layer[1] w0.5: C20.1@17.1,-34.4 FB2.1@17.1,-32.2 ; C20.1@17.325,-34.625 U5.18@21.375,-34.625
D_N: C1.1 CN1.2 D-.TP R2.2 | length 7.9
  Top Layer[1] w0.2: C1.1@33.777,4.8 C1.1@34.2,4.8 ; R2.2@34.3,3 33.677,3.623 33.677,6.955 35.375,8.653 CN1.2@35.375,9.47
  other v1: 34.342,5.451
D_P: C2.1 CN1.3 D+.TP R1.1 | length 8
  Top Layer[1] w0.2: R1.1@32.6,3 33.223,3.623 33.223,7.151 34.725,8.653 CN1.3@34.725,9.47 ; C2.1@32.6,4.8 33.223,4.8
  other v1: 32.31,5.451
DTR_3V3: U1.1 U6.2 | length 2.8
  Top Layer[1] w0.2: U6.2@27.343,-15.018 U1.1@27.343,-12.2
DTR_5V: C16.1 U6.4 | length 48.4
  Top Layer[1] w0.2: v1@13.164,-24.394 21.515,-24.394 26.75,-19.159 U6.4@26.75,-17.125 ; v1@18.8,-51.6 C16.1@19.7,-51.6
  Bottom Layer[2] w0.2: v1@13.054,-24.442 13.054,-27.729 12.752,-28.031 12.752,-43.301 18.7,-49.249 v1(18.7,-51.6)
  other v1: 13.006,-24.394
GATE1: C15.1 D2.1 Q1.1 Q2.1 R12.1 | length 13.8
  Top Layer[1] w0.2: Q2.1@37.65,-2.05 39.55,-3.95 Q1.1@39.55,-5.65 40.132,-5.65 v1@40.438,-5.344 ; v1(41.327,-2.169) R12.1@42.169,-2.169 ; R12.1@42.4,-2.4 C15.1@42.4,-0.7 ; C15.1@42.597,-0.772 D2.1@42.597,1.478 ; C15.1@42.7,-0.8 C15.1@42.75,-0.75
  Bottom Layer[2] w0.2: v1(40.565,-5.344) 41.327,-4.582 v1(41.327,-2.169)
